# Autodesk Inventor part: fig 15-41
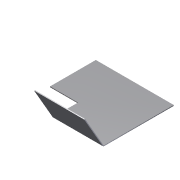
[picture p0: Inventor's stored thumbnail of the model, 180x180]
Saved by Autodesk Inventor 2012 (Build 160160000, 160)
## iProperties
Created: 2005-03
Part Number: fig 15-41
Document SubType Name: Sheet Metal
Designer: CADCIM
Manufacturer: Standard
Standards Organization: Custom
Density: 1 g/cm^3
Sheet Metal Rule: Default
Material: Default
Author: CADCIM
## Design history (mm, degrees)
node "Face1"
  sketch "Sketch1"
    geometry: L1 (31.393, 35.714)-(-19.875, 35.714); L2 (-19.875, 35.714)-(-19.875, 5.625); L3 (-19.875, 5.625)-(-1.5, 5.625); L4 (-1.5, 5.625)-(-1.5, -10.705); L5 (-1.5, -10.705)-(31.393, -10.705); L6 (31.393, -10.705)-(31.393, 35.714)
    constraints: 12 end point, 4 parallel, 1 horizontal, 1 perpendicular
sketch "Sketch3"
  geometry: L1 (18.375, -30.089)-(18.375, 0); L2 (18.375, -46.42)-(18.375, -30.089) reference; L3 (18.375, -30.089)-(0, -30.089) reference; L4 (0, 0)-(51.268, 0) reference
  constraints: 3 point on line, 2 end point, 1 vertical
node "Flange1"
body "Solid1"
face "Plate1" dims "Thickness" = 0.5
sketch "Sketch4"
  geometry: L1 (0, 25)-(-32.893, 25); L2 (-32.893, 25)-(-32.893, 0); 2 other entities
  constraints: 4 end point, 4 other
face "Plate2" dims "d1" = 0.5 (= BendReliefWidth), "d2" = 0.25 (= BendReliefDepth), "d3" = 1 (= MinimumRemnant), "d4" = 0.5 (= BendRadius), "d5" = 25, "d6" = 60 deg, "d7" = 0.5 (= BendRadius), "d8" = 2 (= CornerReliefSize), "d9" = 0.5 (= GapSize), "d10" = 0.5 (= JacobiRadiusSize), "SeamGap" = 0.01, "Thickness" = 0.5
bend "Bend1" dims "d1" = 0.5 (= BendReliefWidth), "d2" = 0.25 (= BendReliefDepth), "d3" = 1 (= MinimumRemnant), "d4" = 0.5 (= BendRadius), "d5" = 25, "d6" = 60 deg, "d7" = 0.5 (= BendRadius), "SeamGap" = 0.01, "Thickness" = 0.5
feature "Corner1" dims "d5" = 25, "d6" = 60 deg, "d8" = 2 (= CornerReliefSize), "d9" = 0.5 (= GapSize), "d10" = 0.5 (= JacobiRadiusSize)
other parameters: "BendRadius" = 0.5 (= Thickness), "BendReliefWidth" = 0.5 (= Thickness), "BendReliefDepth" = 0.25 (= 0.5 x Thickness), "CornerReliefSize" = 2 (= 4 x Thickness), "MinimumRemnant" = 1 (= 2 x Thickness), "TransitionRadius" = 0.5 (= BendRadius), "d0" = 0.5 (= BendRadius), "JacobiRadiusSize" = 0.5 (= Thickness), "GapSize" = 0.5 (= Thickness)
